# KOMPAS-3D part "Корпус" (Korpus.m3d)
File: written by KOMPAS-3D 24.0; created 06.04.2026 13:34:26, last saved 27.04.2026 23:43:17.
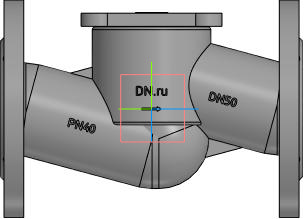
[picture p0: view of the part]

Document properties: Автор: R2D2; Полное имя файла: C:\Работа\ГОТОВЫЕ ИСХОДНИКИ\VSO2130M-F-S Клапан запорный сальниковый DN.ru Ду15-100 Ру40\исходные материалы\DN50\Korpus.m3d

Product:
- Body: Труба / Нестандартная труба / L = 147.7 мм  | qty 1  | 2 such rows
    Материал: Нестандартная труба (density 7856 kg/m3)
    Масса: 14.295401
    Раздел спецификации: Детали
    Примечание: 4,47 кг
    additional columns: Pipeline; 0.07; 0; 0; 0.002; 0.14772; true; 0.04
- Body: Тело 4  | qty 1
    Материал: Нестандартная труба (density 7856 kg/m3)
    Масса: 14.295401
- Body: Тело 5  | qty 1
    Материал: Нестандартная труба (density 7856 kg/m3)
    Масса: 14.295401
- Body: Тело 8  | qty 1
    Материал: Нестандартная труба (density 7856 kg/m3)
    Масса: 14.295401
- Body: Тело 10  | qty 1
    Материал: Нестандартная труба (density 7856 kg/m3)
    Масса: 14.295401
- Body: Тело 11  | qty 1
    Материал: Нестандартная труба (density 7856 kg/m3)
    Масса: 14.295401
- Body: Тело 12  | qty 1
    Материал: Нестандартная труба (density 7856 kg/m3)
    Масса: 14.295401
- Body: Тело 13  | qty 1
    Материал: Нестандартная труба (density 7856 kg/m3)
    Масса: 14.295401
- Part/product: Корпус
    Масса: 6.9

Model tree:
1. Труба:1  (labels: {F703FF30-5BE6-4673-A7F1-8EDA1BE1E2D1}; SHAPEOBJECT3D_ATTR_BUTT; SHAPEOBJECT3D_ATTR_VALID; SHAPEOBJECT3D_ATTR_BUTT_AREA)
     PIPE_R = 3
2. Труба:2  (labels: {F703FF30-5BE6-4673-A7F1-8EDA1BE1E2D1}; SHAPEOBJECT3D_ATTR_BUTT; SHAPEOBJECT3D_ATTR_VALID; SHAPEOBJECT3D_ATTR_BUTT_AREA)
     PIPE_R = 3
3. Колонна
4. Элемент выдавливания:1
     Смещение 1 = -1; Смещение 2 = -5
5. Скругление:17  (with: Ребро.Элемент выдавливания:1)
     Радиус = 2
6. Скругление:18  (with: Ребро.Элемент выдавливания:1)
7. Скругление:24
     Радиус = 1.5
8. Элемент выдавливания:2
     Расстояние 1 = 6
9. Эскиз:4  (with: Грань.Элемент выдавливания:1)
10. Элемент выдавливания:3
     Расстояние 1 = 0.5
11. ОТЛИВКА
12. Скругление:6  (with: Грань.Элемент выдавливания:1)
     Радиус = 2
13. Элемент выдавливания:6  (with: Грань.Элемент выдавливания:1)
     Смещение 1 = 4
14. ЛЕЙБЛ
15. Элемент выдавливания:7  (with: Грань.Элемент выдавливания:1)
     Расстояние 1 = 45.9793; Смещение 1 = 1
16. Dn
17. Pn
18. Стрелочка
19. Элемент выдавливания:10  (with: Грань.Труба:1)
     Расстояние 1 = 35.8203; Смещение 1 = 1
20. Элемент выдавливания:11  (with: Грань.Труба:2)
     Расстояние 1 = 35.9787; Смещение 1 = 1
21. Элемент выдавливания:12  (with: Грань.Элемент выдавливания:1)
     Расстояние 1 = 45.9998; Смещение 1 = 1
22. Материал
23. Элемент выдавливания:13  (with: Грань.Элемент выдавливания:1)
     Расстояние 1 = 45.4944; Смещение 1 = 0.5
24. Фланец верх  (with: Грань.Элемент выдавливания:3)
25. Элемент выдавливания:14
     Расстояние 1 = 10
26. Эскиз:18  (with: Грань.Элемент выдавливания:14)
27. Элемент выдавливания:15
     Расстояние 1 = 0.5
28. Эскиз:19  (with: Грань.Элемент выдавливания:14, Ребро.Элемент выдавливания:14)
29. Элемент выдавливания:16  (with: Грань.Элемент выдавливания:14)
     Расстояние 1 = 0.5; Расстояние 2 = 11; Смещение 2 = 1
30. Фланец
31. Элемент вращения:1
     Угол 1 = 360
32. отвертие во фланце  (with: Грань.Элемент вращения:1)
33. Элемент выдавливания:8
34. Массив по концентрической сетке:2  (with: Элемент выдавливания:8, Эскиз:10, Грань.Элемент вращения:1)  (4 pattern instances)
     Шаг 2 = 360
35. Зеркальный массив:1
36. Экземпляр ( 1 )
37. Экземпляр ( 2 )  (with: Элемент вращения:1, Массив по концентрической сетке:2, Экземпляр ( 1 ), Элемент выдавливания:8)
38. Экземпляр ( 3 )  (with: Элемент выдавливания:8)
39. Экземпляр ( 4 )  (with: Элемент выдавливания:8)
40. Скругление:25  (with: Ребро.Элемент выдавливания:1)
     Радиус = 2
41. Массив по концентрической сетке:3  (with: Элемент выдавливания:16, Эскиз:19)  (labels: Клапан запорный DN.ru Ду50 Ру40)  (4 pattern instances)
     Шаг 2 = 360

Expressions: DS/2+3; DN/2; LL/2; D1/2; D2/2-10
Referenced files in C:\Работа\ГОТОВЫЕ ИСХОДНИКИ\VSO2130M-F-S Клапан запорный сальниковый DN.ru Ду15-100 Ру40\исходные материалы\DN50\: VSO2130M-F-S Клапан запорный DN.ru Ду50 Ру40.a3d
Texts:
  GOST 26.020 Pr3
  var3D
  GS-C25
  смещение колонны вниз
  LL-10
  DN+20
  DS+15
  Труба / Нестандартная труба / L = %s мм
  Ось Y.Начало координат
